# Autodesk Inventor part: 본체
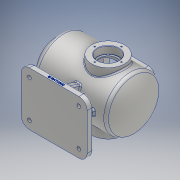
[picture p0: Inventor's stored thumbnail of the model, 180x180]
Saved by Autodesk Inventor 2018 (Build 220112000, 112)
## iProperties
Created: 2021-11
Part Number: 본체
Material: 알루미늄 6061
Document SubType Name: Modeling
Designer: 1class2
Density: 2.7 g/cm^3
Appearance: 알루미늄 - 평지
Mass: 3572.18 g
Surface Area: 2426.36 cm^2
Volume: 1323.03 cm^3
Author: 1class2
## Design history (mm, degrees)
sketch "스케치1"
  geometry: L1 (80, 65)-(-80, 65); L2 (-80, 65)-(-80, -65); L3 (-80, -65)-(80, -65); L4 (80, -65)-(80, 65); L5 (80, 65)-(-80, -65); L6 (-80, 65)-(80, -65); 1 further point
  constraints: 12 end point, 2 midpoint, 2 parallel, 1 horizontal, 1 perpendicular
  dimensions: "d0" = 160 distance of L2.end L3.end; "d1" = 130 distance of L1.end L2.end
extrude "돌출1" new body sketch "스케치1" distance "d2" = 14; taper "d3" = 0 deg
sketch "스케치2"
  geometry: L1 (-155.073, 114)-(104.111, 114); L2 (-85, 146.5)-(-110, 146.5); L3 (-110, 146.5)-(-110, 161.5); L4 (-110, 161.5)-(-100, 161.5); L5 (-100, 161.5)-(-100, 179); L6 (-100, 179)-(75.993, 179); L7 (-85, 146.5)-(-85, 169); L8 (-85, 169)-(71.239, 169); L9 (90, 114)-(100, 114); L10 (-80, 0)-(-80, 14) reference; L11 (100, 54.333)-(100, 167.179); A1 r 100 centre (0, 114) between (100, 114) and (75.993, 179); A2 r 90 centre (0, 114) between (90, 114) and (71.239, 169); 1 further point
  constraints: 20 end point, 5 perpendicular, 4 point on circle, 3 horizontal, 3 point on line, 2 centre point, 2 vertical, 1 concentric, 1 tangent
  dimensions: "d4" = 114 vertical distance of L1.end point (0, 0); "d5" = 100 radius of A1; "d6" = 210 distance from line of L3 L9.end; "d7" = 130 diameter of L6 L1; "d8" = 110 diameter of L8 L1; "d9" = 95 diameter of L4 L1; "d11" = 65 diameter of L2 L1; "d12" = 10 distance between parallel lines of L5 L3; "d13" = 30 distance between parallel lines of L3 L10; "d14" = 25 distance of L2.start L2.end; "d15" = 10 radial gap between concentric circles of A1 A2
revolve "회전1" sketch "스케치2" stored, may be unused: angle "d16" = 90 deg
node "작업 평면1"
sketch "스케치3"
  geometry: L1 (75, 0)-(-75, 0); L2 (75, 26)-(75, 40); L3 (75, 40)-(49, 40); L4 (49, 40)-(49, 26); L5 (49, 26)-(75, 26); 2 further points
  constraints: 10 end point, 3 perpendicular, 2 vertical alignment, 1 horizontal, 1 midpoint, 1 vertical
  dimensions: "d18" = 114 vertical distance of L1.start point (0, -114); "d19" = 150 distance of L1.start L1.end; "d20" = 80 diameter of L3 L1; "d21" = 52 diameter of L5 L1; "d22" = 26 distance of L2.end L3.end
revolve "회전2" sketch "스케치3" stored, may be unused: angle "d23" = 90 deg
sketch "스케치13"
  geometry: C1 r 40 at (0, 0) reference; A1 r 32.5 centre (0, 0) between (0, 32.5) and (32.5, 0); 3 further points
  constraints: 4 point on circle, 2 horizontal alignment, 2 vertical alignment, 1 centre point, 1 concentric
  dimensions: "d82" = 65 diameter of A1
hole "구멍4" sketch "스케치13" at (0, 32.5), (32.5, 0), (0, -32.5), (-32.5, 0) diameter "d83" = 3.242; stored, may be unused: countersink angle "d87" = 90 deg, drill point angle "d89" = 118 deg; dims "d84" = 11, "d85" = 4, "d86" = 2, "d88" = 13
sketch "스케치15"
  geometry: C1 r 26 at (0, 0) reference; 1 further point
extrude "돌출7" cut sketch "스케치15" distance "d98" = 18; taper "d99" = 0 deg
node "작업 평면2"
sketch "스케치4"
  geometry: L1 (-128.655, 0)-(162.583, 0); L2 (-60, 30)-(60, 30); L3 (60, 30)-(60, -30); L4 (60, -30)-(-60, -30); L5 (-60, -30)-(-60, 30); L6 (-60, 30)-(60, -30); L7 (60, 30)-(-60, -30); L8 (-110, -47.5)-(-110, 47.5) reference; 2 further points
  constraints: 14 end point, 2 horizontal, 2 midpoint, 2 parallel, 2 point on line, 1 perpendicular
  dimensions: "d25" = 50 distance between parallel lines of L5 L8; "d26" = 120 distance of L3.end L4.end; "d27" = 60 distance of L2.end L3.end
extrude "돌출2" join sketch "스케치4" stored distance "d28" = 14; taper "d29" = 0 deg
sketch "스케치5"
  geometry: C1 r 21 at (0, 0); C2 r 40 at (0, 0) reference; 1 further point
  constraints: 1 centre point, 1 concentric
  dimensions: "d30" = 42 diameter of C1
extrude "돌출3" cut sketch "스케치5" extent not by distance; stored distance "d31" = 14; taper "d32" = 0 deg
sketch "스케치7"
  geometry: L1 (-50, -20)-(50, -20); L2 (50, -20)-(50, 20); L3 (50, 20)-(-50, 20); L4 (-50, 20)-(-50, -20); L5 (-50, -20)-(50, 20); L6 (50, -20)-(-50, 20); L7 (60, 30)-(-60, 30) reference; L8 (60, -30)-(60, 30) reference; 1 further point
  constraints: 12 end point, 2 midpoint, 2 parallel, 1 horizontal, 1 perpendicular
  dimensions: "d33" = 10 distance between parallel lines of L7 L3; "d34" = 10 distance between parallel lines of L8 L2
extrude "돌출4" cut sketch "스케치7" distance "d35" = 52.25; taper "d36" = 0 deg
sketch "스케치8"
  geometry: L1 (80, 14)-(-80, 14) reference; L2 (-60, 14)-(-44.713, 56); L3 (0, 0)-(0, 80.359); L4 (60, 14)-(44.713, 56); L5 (-100, 49)-(75.993, 49) reference; L6 (-44.713, 56)-(44.713, 56); L7 (60, 14)-(-60, 14)
  constraints: 10 end point, 2 point on line, 1 collinear, 1 horizontal, 1 vertical, 1 other
  dimensions: "d37" = 120 distance of L2.start L4.start; "d38" = 110 deg angle of L1 L4; "d39" = 42 distance between parallel lines of L1 L6
extrude "돌출5" join sketch "스케치8" stored distance "d40" = 14; taper "d41" = 0 deg
sketch "스케치9"
  geometry: L1 (14, -50)-(58.485, -33.809); L2 (14, 65)-(14, -65) reference; 2 further points
  constraints: 2 end point, 1 point on line, 2 other
  dimensions: "d42" = 50 vertical distance of point (0, 0) L1.start; "d43" = 110 deg angle of L2 L1
feature "리브1" sketch "스케치9" dims "d44" = 1, "d45" = 14, "d46" = 0, "d47" = 0, "d48" = 1, "d49" = 1
sketch "스케치10"
  geometry: L1 (60, 45)-(-60, 45); L2 (-60, 45)-(-60, -45); L3 (-60, -45)-(60, -45); L4 (60, -45)-(60, 45); L5 (60, 45)-(-60, -45); L6 (-60, 45)-(60, -45); L7 (-80, -65)-(80, -65) reference; L8 (-80, 65)-(-80, -65) reference; 1 further point
  constraints: 12 end point, 2 midpoint, 2 parallel, 1 horizontal, 1 perpendicular
  dimensions: "d50" = 20 distance between parallel lines of L7 L3; "d51" = 20 distance between parallel lines of L8 L2
hole "구멍1" sketch "스케치10" at (60, 45), (-60, 45), (-60, -45), (60, -45) diameter "d52" = 9; stored, may be unused: countersink angle "d56" = 90 deg, drill point angle "d58" = 118 deg; dims "d53" = 6, "d54" = 18, "d55" = 2, "d57" = 8
sketch "스케치11"
  geometry: C1 r 47.5 at (0, 0) reference; A1 r 40 centre (0, 0) between (0, 40) and (40, 0); 3 further points
  constraints: 4 point on circle, 2 horizontal alignment, 2 vertical alignment, 1 centre point, 1 concentric
  dimensions: "d59" = 80 diameter of A1
hole "구멍2" sketch "스케치11" at (0, 40), (40, 0), (0, -40), (-40, 0) diameter "d60" = 3.242; stored, may be unused: countersink angle "d64" = 90 deg, drill point angle "d66" = 118 deg; dims "d61" = 11, "d62" = 4, "d63" = 2, "d65" = 13
sketch "스케치12"
  geometry: L1 (-55, -25)-(55, -25); L2 (55, -25)-(55, 25); L3 (55, 25)-(-55, 25); L4 (-55, 25)-(-55, -25); L5 (-55, -25)-(55, 25); L6 (55, -25)-(-55, 25); 5 further points
  constraints: 12 end point, 6 midpoint, 2 parallel, 1 horizontal, 1 perpendicular
  dimensions: "d67" = 50 distance of L1.end L2.end; "d68" = 110 distance of L2.end L3.end
hole "구멍3" sketch "스케치12" at (0, 25), (0, -25), (55, 0), (-55, 0) diameter "d69" = 3.242; stored, may be unused: countersink angle "d73" = 90 deg, drill point angle "d75" = 118 deg; dims "d70" = 9, "d71" = 4, "d72" = 2, "d74" = 11
fillet "R3 외 필렛" dims "d76" = 20, "d77" = 10, "d78" = 5, "d79" = 15, "d80" = 0.3
fillet "R3" dims "d81" = 3
chamfer "C1" distance "d90" = 1; stored, may be unused: second distance "d91" = 2, angle "d92" = 45 deg
sketch "스케치14"
  geometry: L1 (35, 7.5)-(85, 7.5); L2 (85, 7.5)-(85, 2.5); L3 (85, 2.5)-(35, 2.5); L4 (35, 2.5)-(35, 7.5); L5 (35, 2.5)-(85, 2.5); L6 (85, 2.5)-(85, 7.5); L7 (85, 7.5)-(35, 7.5); L8 (35, 7.5)-(35, 2.5); L9 (35, 2.5)-(85, 7.5); L10 (85, 2.5)-(35, 7.5); L11 (0, 0)-(120, 0) reference; 4 further points
  constraints: 12 end point, 4 midpoint, 2 coincident, 2 parallel, 1 horizontal, 1 perpendicular, 1 vertical alignment, 2 other
  dimensions: "d93" = 5 distance of point (60, 0) point (60, 5); "d94" = 5 distance of L7.end L5.start; "d95" = 50 distance of L6.end L7.end
extrude "돌출6" join sketch "스케치14" distance "d96" = 0.5; taper "d97" = 0 deg
sketch "스케치16"
  geometry: L1 (-127.268, 114)-(140, 114); L2 (-30, 114)-(60, 114); L3 (60, 114)-(60, 169); L4 (60, 169)-(-30, 169); L5 (-30, 169)-(-30, 114); 1 further point
  constraints: 10 end point, 2 horizontal, 2 parallel, 1 perpendicular, 1 point on line
  dimensions: "d100" = 114 vertical distance of point (0, 0) L1.end; "d101" = 80 distance from line of L1.end L3; "d102" = 90 distance of L3.end L4.end; "d103" = 140 horizontal distance of point (0, 0) L1.end; "d104" = 110 diameter of L4 L1
revolve "회전3" sketch "스케치16" stored, may be unused: angle "d105" = 90 deg
node "솔리드1"
mirror "미러1"
mirror "미러2"
other parameters: "d17" = -127, "d24" = -184
